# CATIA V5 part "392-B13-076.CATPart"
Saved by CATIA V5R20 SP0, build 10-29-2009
Part number: 392-B13-076
Definition: NONE
Nomenclature: 392-B13-076
Source: Unknown
Description: 392-B13-076
Bounding box of the stored display mesh (mm): x 0 to 76, y -6.145 to 6.145, z -6.1 to 5.947
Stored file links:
  C:\Users\Utente\Desktop\IO LAVORO\3D X SITO CF\X SITO\3D files 392B\392-B13-076.CATPart
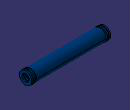
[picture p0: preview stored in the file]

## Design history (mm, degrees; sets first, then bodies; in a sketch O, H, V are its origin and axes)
Body1 "392-B13-076" (main body)
  Solid1: solid without history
